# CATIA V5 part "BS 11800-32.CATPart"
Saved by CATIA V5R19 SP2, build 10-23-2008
Part number: BS 11800-32
Bounding box of the stored display mesh (mm): x -74.81 to 74.81, y -74.81 to 74.81, z 0 to 142
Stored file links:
  C:\Users\Bora\Desktop\3D Katı model\BS serisi\BS 11800\BS 11800-32.CATPart
  C:\Program Files\Dassault Systemes\B19\intel_a\reffiles\standard\MetricThickPitch.txt
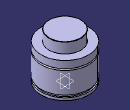
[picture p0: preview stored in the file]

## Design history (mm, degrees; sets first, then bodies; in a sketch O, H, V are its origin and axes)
Body1 (main body)
  Sketch1 on yz-plane, origin (0, 0, 0), H (0, 1, 0), V (0, 0, 1)
    point P1 (75, 87)
    point P2 (75, 82)
    point P5 (50, 141)
    point P7 (50, 141)
    point P12 (75, 82)
    point P13 (75, 87)
    arc A1 centre (75, 84.5) radius 2.5 from (75, 87) to (75, 82) ccw
    line L1 (75, 0) -> (75, 8)
    line L2 (50, 141) -> (50, 109)
    arc A2 centre (49, 141) radius 1 from (50, 141) to (49, 142) ccw
    line L3 (71, 15) -> (71, 8)
    line L4 (75, 15) -> (75, 82)
    line L5 (75, 87) -> (75, 109)
    line L6 (49, 142) -> (0, 142)
    line L7 (50, 109) -> (75, 109)
    line L8 (0, 0) -> (75, 0)
    line L9 (71, 15) -> (75, 15)
    line L10 (71, 8) -> (75, 8)
    tangency: L6 A2
    horizontal: L7 H, L8 H, L9 H, L10 H
    coincidence: P1 P13, P2 P12, P5 P7
  Shaft1: profile Sketch1, axis Sketch1.V, angle 360
  Sketch2 on face of Shaft1 from Sketch1.L8, origin (0, 0, 0), H (1, 0, 0), V (0, -1, 0)
    point P1 (50, 0)
    distance P1 V = 50
  Hole1: placed by Sketch2, at (50, 0, 0) direction (0, 0, 1), diameter 8.376, depth 12, threaded "M10", thread diameter 10, thread depth 12, pitch 1.5
  CircPattern1: of Hole1, instances 4, angular step 90, axis from xy-plane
